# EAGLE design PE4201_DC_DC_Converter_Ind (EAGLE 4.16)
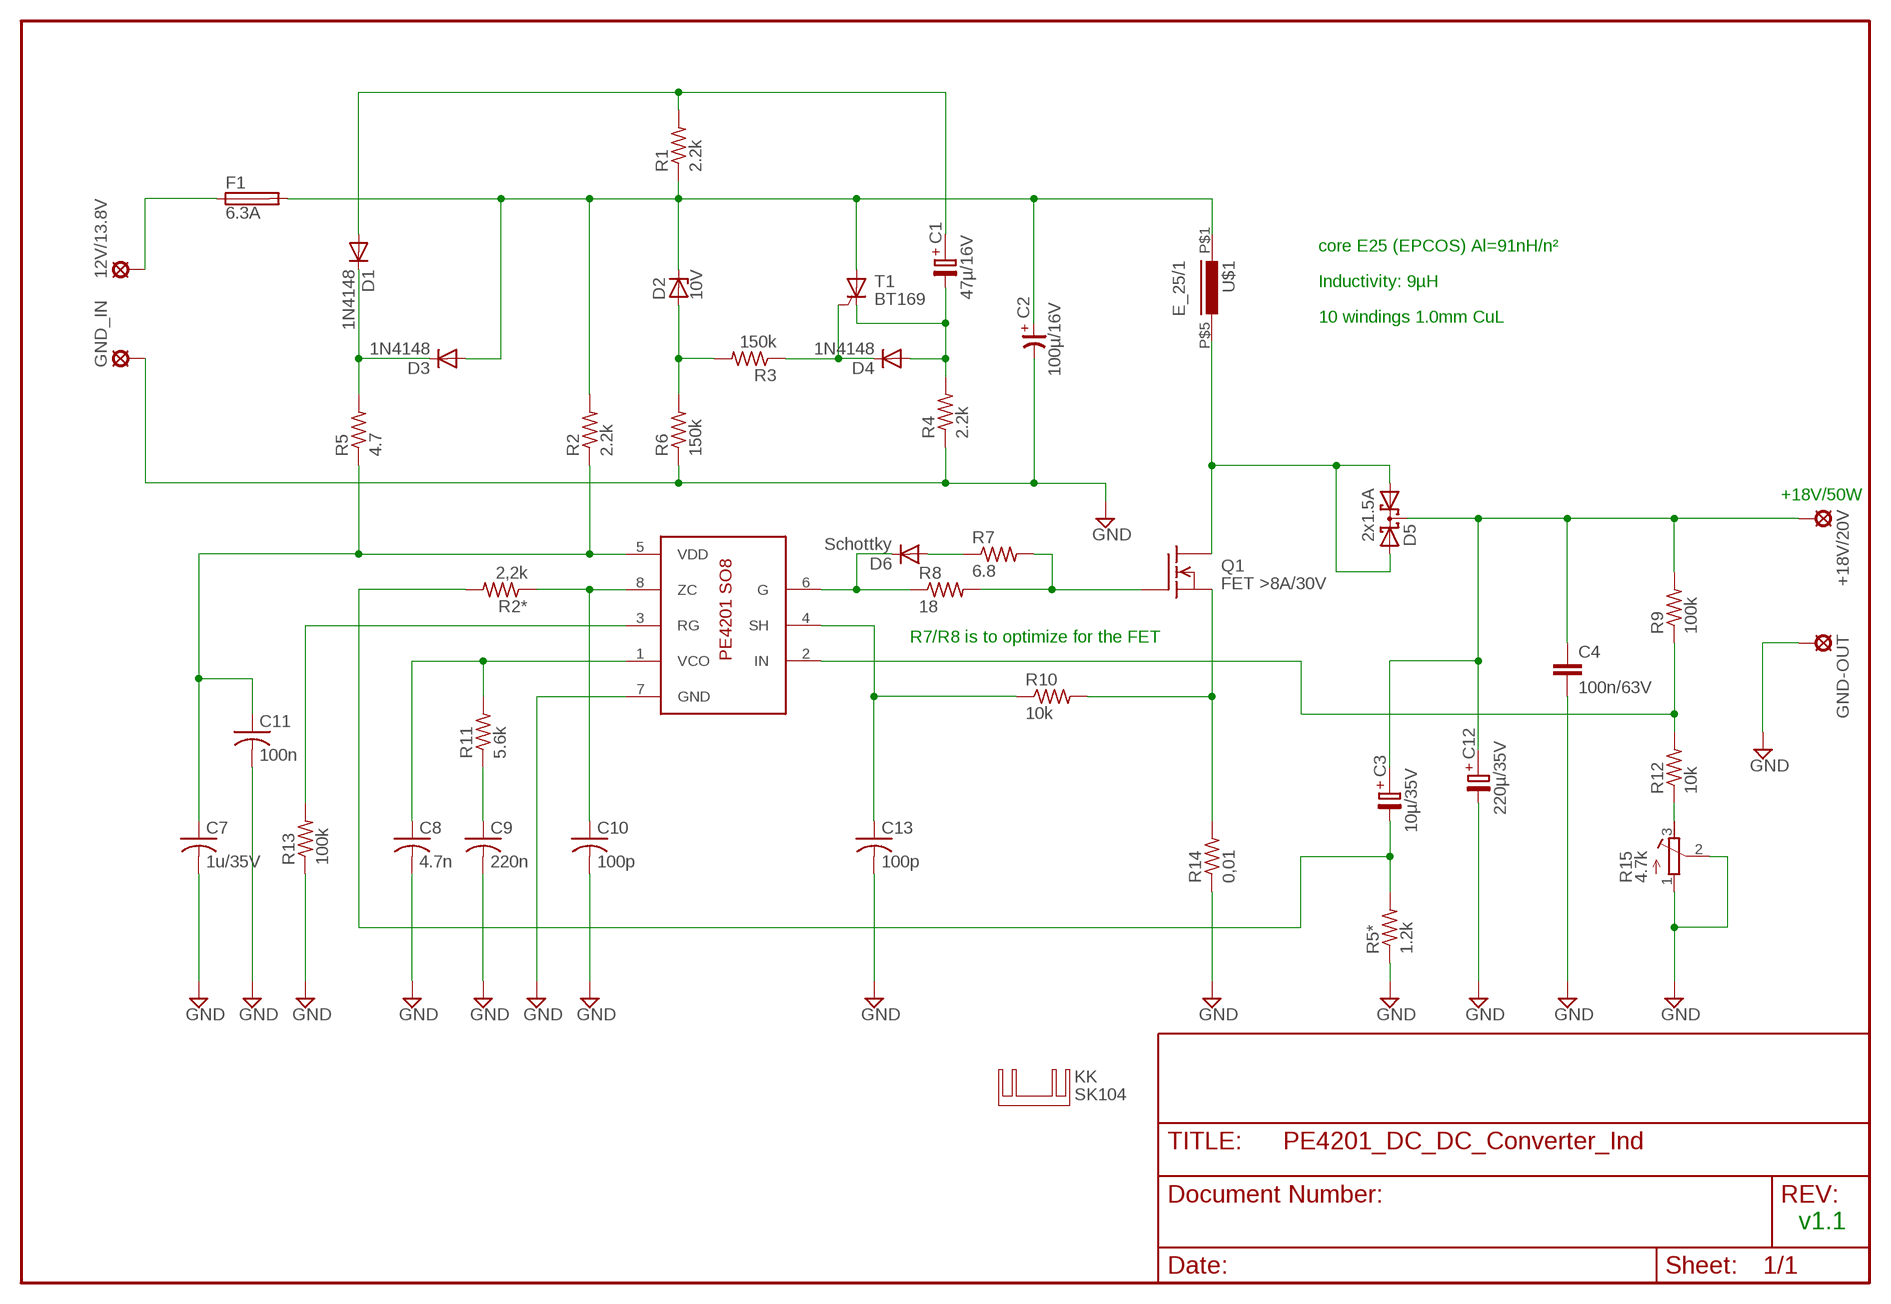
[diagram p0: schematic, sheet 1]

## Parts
12V/13.8V  SE14  [SE14]
+18V/20V  SE14  [SE14]
C1  47µ/16V  C-PR-2,5X6,5  [E2,5-6,5]
C2  100µ/16V  CP-E-035X100  [E-035X100]
C3  10µ/35V  C-PR-2,5X6  [E2,5-6]
C4  100n/63V  C7.5/4  [C7.5B4]
C7  1u/35V  C-US050-030X075  [C050-030X075]
C8  4.7n  C-US050-030X075  [C050-030X075]
C9  220n  C-US050-030X075  [C050-030X075]
C10  100p  C-US050-030X075  [C050-030X075]
C11  100n  C-US050-030X075  [C050-030X075]
C12  220µ/35V  C-PR-5,0X12  [E5,0-12]
C13  100p  C-US050-030X075  [C050-030X075]
D1  1N4148  [DO35-10]
D2  10V  ZENER-DIODEDO35Z10  [DO35Z10]
D3  1N4148  [DO35-10]
D4  1N4148  [DO35-10]
D5  2x1.5A  DIODE_2SCHOTTKY-SOT82V  [SOT82S]
D6  Schottky  1N4148  [DO35-10]
F1  6.3A  SH22,5A  [SH22,5A]
GND-OUT  SE14  [SE14]
GND_IN  GND  SE14  [SE14]
KK  SK104  [SK104]
Q1  FET >8A/30V  FQA24N50  [TOP3V]
R1  2.2k  R-US_0207/10  [0207/10]
R2  2.2k  R-US_0207/10  [0207/10]
R2*  2,2k  R-US_0207/10  [0207/10]
R3  150k  R-US_0207/10  [0207/10]
R4  2.2k  R-US_0207/10  [0207/10]
R5  4.7  R-US_0207/10  [0207/10]
R5*  1.2k  R-US_0207/10  [0207/10]
R6  150k  R-US_0207/10  [0207/10]
R7  6.8  R-US_0207/10  [0207/10]
R8  18  R-US_0207/10  [0207/10]
R9  100k  R-US_0207/10  [0207/10]
R10  10k  R-US_0207/10  [0207/10]
R11  5.6k  R-US_0207/10  [0207/10]
R12  10k  R-US_0207/10  [0207/10]
R13  100k  R-US_0207/10  [0207/10]
R14  0,01  R-US_0617/22  [0617/22]
R15  4.7k  R-TRIMM3339P  [RTRIM3339P]
T1  BT169  [TO92-2]
U$1  E_25/1  [E25L]
U$2  PE4201/4301_SO08  PE4201_SO08  [PE4201_SO08]

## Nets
++: C13.1 R10.1 U$2.4(SH)
A1: C7.1 C11.1 R2.1 R5.1 U$2.5(VDD)
A3: R13.2 U$2.3(RG)
A4: C8.1 R11.2 U$2.1(VCO)
B3: R9.1 R12.2 U$2.2(IN)
CS/ZC: C10.1 R2*.1 U$2.8(ZC)
GND: C2.- C4.2 C7.2 C8.2 C9.2 C10.2 C11.2 C12.- C13.2 GND-OUT.MP GND_IN.MP R4.1 R5*.1 R6.1 R13.1 R14.1 R15.1(E) R15.2(S) U$2.7(GND)
N$1: D4.C R3.1 T1.G
N$2: C1.- D4.A R4.2 T1.C
N$3: D2.A R3.2 R6.2
N$4: C1.+ D1.A R1.2
N$5: C2.+ D2.C D3.A F1.2 R1.1 R2.2 T1.A U$1.P$1
N$6: D6.C R8.1 U$2.6(G)
N$7: D1.C D3.C R5.2
N$8: Q1.S R10.2 R14.2
N$9: D6.A R7.1
N$10: Q1.G R7.2 R8.2
N$11: D5.A1 D5.A2 Q1.D U$1.P$5
N$12: 12V/13.8V.MP F1.1
N$19: +18V/20V.MP C3.+ C4.1 C12.+ D5.C R9.2
N$22: C9.1 R11.1
N$28: R12.1 R15.3(A)
N$29: C3.- R2*.2 R5*.2

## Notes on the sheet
- core E25 (EPCOS) Al=91nH/n²
- Inductivity: 9µH
- 10 windings 1.0mm CuL
- +18V/50W
- R7/R8 is to optimize for the FET
- v1.1

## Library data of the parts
12V/13.8V +18V/20V GND-OUT GND_IN = solpad:SE14: SOLDER PAD
C1 C3 C12 = cap-pan40:C-PR: POLARIZED ELECTROLYTIC/TANTALUM
C2 = cap-master:CP-: POLARIZED CAP
C4 = capacitor-wima:C: CAPACITOR
C7-C11 C13 = rcl:C-US: CAPACITOR, American symbol
D1 D3 D4 D6 = diode:1N4148: DIODE
D2 = diode:ZENER-DIODE: Z-Diode
D5 = diode:DIODE_2SCHOTTKY-: Dual SCHOTTKY DIODE common cathode
F1 = fuse:SH22,5A: FUSE HOLDER
KK = heatsink:SK104: HEATSINK
Q1 = PE4201:FQA24N50: N-Channel Enhancement MOSFET 400V; 12,5A; 0,4Ohm
R1 R2 R2* R3-R5 R5* R6-R14 = rcl:R-US_: RESISTOR, American symbol
R15 = rcl:R-TRIMM: Trimm resistor
T1 = triac:BT169: THYRISTOR
U$1 = EPCOS-Trafos:E_25/1
U$2 = PE4201:PE4201_SO08

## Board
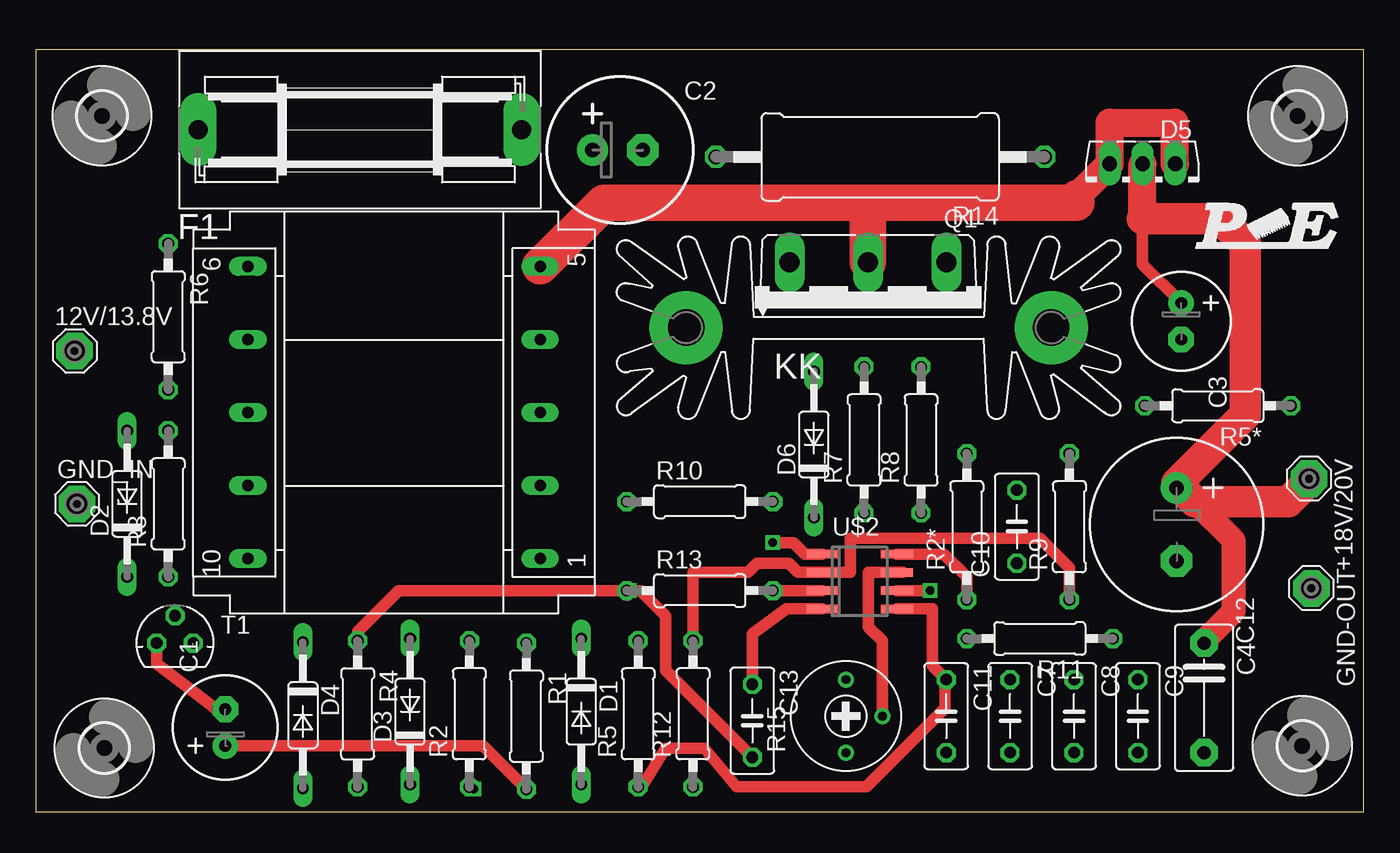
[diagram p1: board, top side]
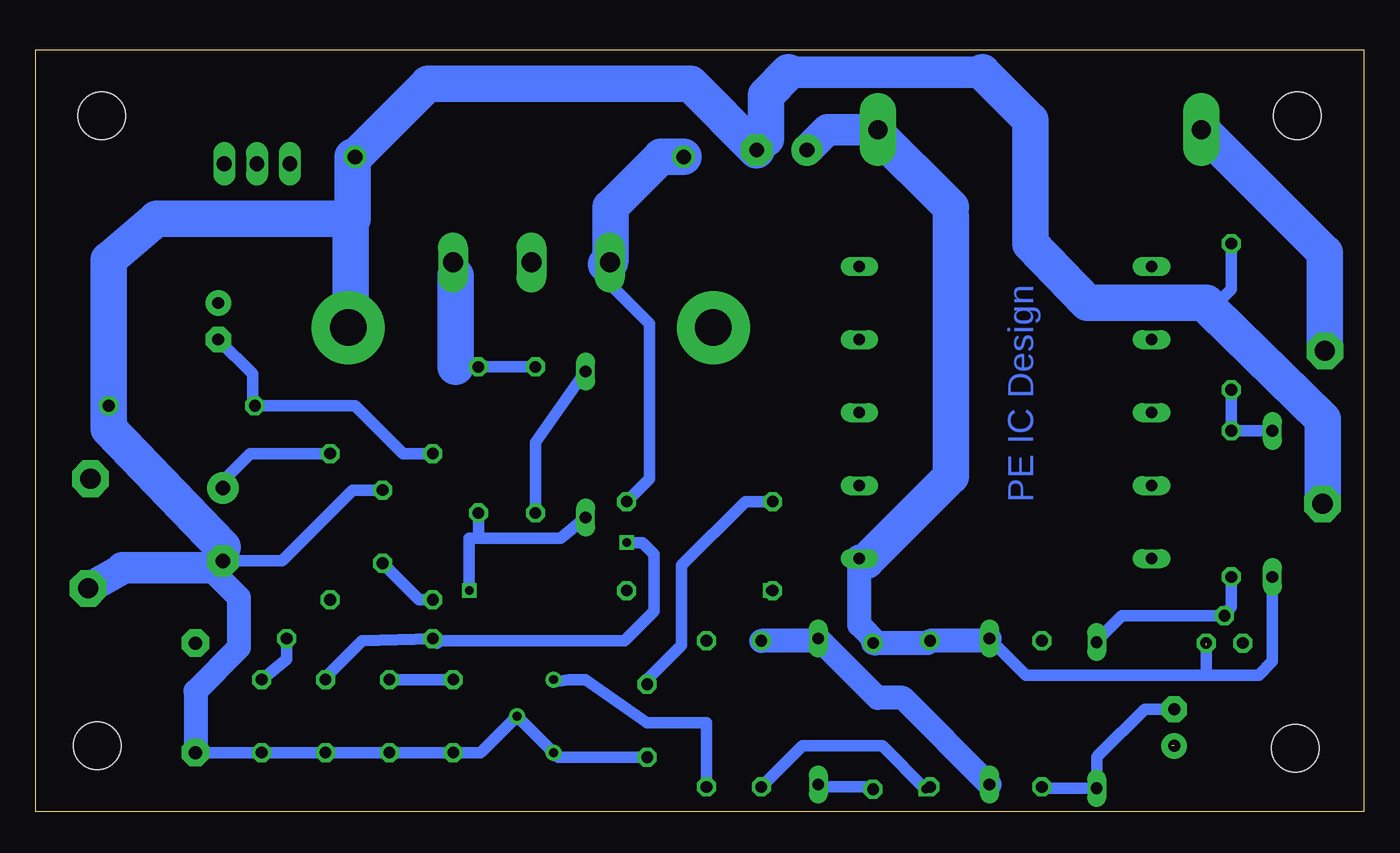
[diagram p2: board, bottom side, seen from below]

Size 92.37 x 53.01 mm. Coordinates in mm from the lower left corner, seen from the top.
Outline: 0,0 92.37,0 92.37,53.01 0,53.01 0,0
Copper layers (1*16): Top 0.035mm / dielectric 1.5mm / Bottom 0.035mm
Design rules "default": minimum track width 10mil, minimum drill 24mil, track to track 8mil, track to pad 8mil, pad to pad 8mil, via to via 8mil, smd to smd 8mil, copper to edge 40mil, drill to drill 8mil, minimum pad ring 10mil, minimum via ring 8mil, stop-mask expansion 4mil, vias tented up to drill 0mil, thermal gap 10mil

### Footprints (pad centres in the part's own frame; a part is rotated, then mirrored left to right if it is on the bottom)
SE14 = drill 1.397 pad 2.54 octagon: MP 0,0
E2,5-6,5 = drill 0.813 pad 1.778 round: + -1.27,0 | drill 0.813 pad 1.778 octagon: - 1.27,0
E-035X100 = drill 1.016 pad 2.184 round: + -1.905,0 | drill 1.016 pad 2.184 octagon: - 1.587,0
E2,5-6 = drill 0.813 pad 1.778 round: + -1.27,0 | drill 0.813 pad 1.778 octagon: - 1.27,0
C7.5B4 = drill 0.914 pad 1.905 octagon: 1 -3.81,0; 2 3.81,0
C050-030X075 = drill 0.813 octagon: 1 -2.54,0; 2 2.54,0
E5,0-12 = drill 1.016 pad 2.184 round: + -2.54,0 | drill 1.016 pad 2.184 octagon: - 2.54,0
DO35-10 = drill 0.813 long: A 5.08,0; C -5.08,0
DO35Z10 = drill 0.813 long: A 5.08,0; C -5.08,0
SOT82S = drill 1.016 long: A1 -2.286,-1.27; A2 2.286,-1.27; C 0,-1.27
SH22,5A = drill 1.321 pad 2.54 long: 1 -11.252,0; 2 11.252,0
SK104 = drill 2.54 pad 5.08 round: A2,5 -12.7,-0.762; B2,5 12.7,-0.762
TOP3V = drill 1.397 long: D 0,-3.175; G -5.461,-3.175; S 5.461,-3.175
0207/10 = drill 0.813 octagon: 1 -5.08,0; 2 5.08,0
0617/22 = drill 1.016 octagon: 1 -11.43,0; 2 11.43,0
RTRIM3339P = drill 0.61 round: 1 -2.54,0; 2 0,-2.54; 3 2.54,0
TO92-2 = drill 0.813 octagon: A 1.27,0; C -1.27,0; G 0,1.905
E25L = drill 0.8 long: P$1 -10.16,-10.16; P$2 -5.08,-10.16; P$3 0,-10.16; P$4 5.08,-10.16; P$5 10.16,-10.16; P$6 10.16,10.16; P$7 5.08,10.16; P$8 0,10.16; P$9 -5.08,10.16; P$10 -10.16,10.16
PE4201_SO08 = smd 0.6 x 2.2: 1 -1.905,-2.6; 2 -0.635,-2.6; 3 0.635,-2.6; 4 1.905,-2.6; 5 1.905,2.6; 6 0.635,2.6; 7 -0.635,2.6; 8 -1.905,2.6
3,3 = hole 3.3: 0,0

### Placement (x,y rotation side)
12V/13.8V  2.69,32.06 0 top
+18V/20V  88.58,23.17 270 top
C1  13.17,5.87 90 top
C2  40.63,46.03 0 top
C3  79.69,34.12 270 top
C4  81.28,7.93 270 top
C7  67.78,6.66 270 top
C8  72.23,6.66 270 top
C9  76.67,6.66 270 top
C10  68.26,19.84 90 top
C11  63.34,6.66 270 top
C12  79.37,20 270 top
C13  49.84,6.34 270 top
D1  37.94,6.98 270 top
D2  6.34,21.42 90 top
D3  26.03,6.98 90 top
D4  18.57,6.72 270 top
D5  76.99,43.81 180 top
D6  54.13,25.55 90 top
F1  22.54,47.46 0 top
GND-OUT  88.74,15.55 270 top
GND_IN  2.85,21.42 0 top
KK  57.94,34.44 0 top
Q1  57.89,35.05 180 top
R1  34.13,6.66 270 top
R2  30.16,6.82 90 top
R2*  64.77,19.84 90 top
R3  9.2,21.42 90 top
R4  22.38,6.82 270 top
R5  41.9,6.82 90 top
R5*  82.23,28.25 180 top
R6  9.2,34.44 270 top
R7  57.62,25.87 90 top
R8  61.59,25.87 90 top
R9  71.91,19.84 90 top
R10  46.19,21.58 0 top
R11  69.84,12.06 180 top
R12  45.71,6.82 90 top
R13  46.19,15.39 0 top
R14  58.73,45.55 180 top
R15  56.35,6.66 90 top
T1  9.68,11.74 0 top
U$1  24.92,27.77 90 top
U$2  57.3,16.03 270 top
U$3  [3,3]  4.6,48.41 0 top
U$4  [3,3]  4.76,4.44 0 top
U$5  [3,3]  88.1,4.6 0 top
U$6  [3,3]  87.78,48.41 0 top
U$7  [LOGO]  81.43,38.57 0 top

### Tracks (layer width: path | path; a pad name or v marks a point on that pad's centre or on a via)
++
  Top 0.813: U$2.4 52.22,14.12 49.84,12.38 49.84,9.2 C13.1
  Bottom 0.813: R10.1 43.02,21.58 47.46,17.14 47.46,11.58 49.84,9.2 C13.1
A1  (via drill 0.6)
  Top 0.813: U$2.5 62.38,14.12 62.38,10.15 63.24,9.3 | 63.24,9.3 C11.1 | 63.24,9.3 63.24,7.2 57.78,1.74 48.73,1.74 46.51,4.44 43.81,4.44 42.06,1.58 42.06,1.74 R5.1 | R2.1 30,1.58 v30.48,1.58
  Bottom 0.813: C7.1 67.78,9.36 67.62,9.2 C11.1 | v30.48,1.58 33.49,4.6 39.05,4.6 41.75,1.9 41.91,1.9 R5.1 | R5.1
A3
  Top 0.813: 51.11,15.55 R13.2 U$2.3
A4  (via drill 0.6)
  Top 0.813: U$2.1 53.49,17.93 52.7,18.73 v51.27,18.73
  Bottom 0.813: v51.27,18.73 50.16,18.73 49.37,17.93 49.37,13.96 51.43,11.9 64.29,11.9 64.45,11.74 R11.2 69.69,11.9 72.39,9.2 C8.1
B3
  Top 0.813: R12.2 45.72,16.66 49.53,16.66 50.16,17.3 52.38,17.3 53.02,16.66 56.51,16.66 U$2.2 56.67,16.66 56.67,19.04 62.54,19.04 65.72,19.04 69.85,19.04 71.91,16.98 R9.1 | R9.1
CS/ZC
  Top 0.813: U$2.8 63.18,17.93 64.77,16.35 R2*.1
  Bottom 0.813: R2*.1 65.72,14.76 67.94,16.98 C10.1
GND  (via drill 0.6)
  Top 0.813: 60.32,16.66 U$2.7 57.94,16.66 57.94,12.85 58.89,11.9 58.89,11.27 R15.2 | v41.27,15.39 42.06,15.39 43.81,13.65 43.81,9.84 C13.2 | C13.2 | R4.1 22.38,12.53 25.24,15.39 40.79,15.39 41.11,15.07 R13.1
  Bottom 0.813: C4.2 C9.2 C8.2 C7.2 C11.2 61.43,4.12 R15.2 R15.1 | R15.1 56.19,3.96 | 49.68,3.8 C13.2 56.03,3.8 R15.1 | v41.27,15.39 R13.1 41.11,15.23 | R6.1 9.2,36.35 10.63,34.92 | C10.2 70.32,22.38 75.24,17.46 C12.- | C12.- | C12.-
  Bottom 1.676: 80.32,16.98 78.26,14.92 78.26,11.42 81.28,8.41 C4.2
  Bottom 2.184: R14.1 70.32,45.56 | 87.31,28.41 87.47,28.41 R5*.1 | 79.37,18.41 C12.- 80.32,16.98 86.36,16.98 86.2,16.98 GND-OUT.MP | 10.63,34.92 10.95,35.39 | 26.51,51.43 40,51.43 | 42.22,46.19 | 42.22,46.19 C2.- | 41.59,46.82 42.22,46.19
  Bottom 2.54: C2.- 46.83,50.63 65.08,50.63 R14.1 | 70.32,45.56 70.32,41.27 83.97,41.27 87.31,38.41 87.31,28.41 | R5*.1 87.31,26.66 79.37,18.41 | GND_IN.MP 2.85,27.3 10.63,34.92 | 10.95,35.39 19.2,35.39 23.17,39.52 23.17,48.1 26.51,51.43 | 40,51.43 41.59,49.84 41.59,46.82
N$1  (1 unrouted)
  Bottom 0.813: R3.1 9.2,14.28 T1.G 16.82,13.65 | D4.C 18.57,11.9 16.82,13.65 | 16.82,13.65
N$2  (1 unrouted)
  Top 0.813: C1.- 12.54,7.14 11.74,7.77 8.41,10.31 T1.C
  Bottom 0.813: D4.A 18.57,1.58 | C1.- 15.24,7.14 18.41,3.96 18.57,3.8 D4.A | R4.2 22.28,1.64 D4.A
N$3  (1 unrouted)
  Bottom 0.813: R3.2 | R3.2 R6.2 | R3.2 | R3.2 D2.A 6.5,26.5
N$4  (1 unrouted)
  Top 0.813: R1.2 31.11,4.6 13.33,4.6 | C1.+ 13.33,4.76
  Bottom 0.813: D1.A 37.94,1.74 34.29,1.74 R1.2 | D1.A
N$5  (1 unrouted)
  Bottom 0.406: 6.35,14.76 | 6.35,14.76 6.35,14.92
  Bottom 0.813: 6.35,14.76 6.35,10.47 7.3,9.52 12.7,9.52 | 10.95,11.58 10.95,9.52 12.7,9.52 | 12.7,9.52 23.49,9.52 D3.A | D2.C | 6.35,14.92 D2.C | 12.7,9.52
  Bottom 1.676: 33.81,11.74 | 33.81,11.74 R1.1 30.32,11.74 R2.2 26.19,11.9 D3.A | U$1.P$1 35.08,13.01 33.81,11.74
  Bottom 1.93: U$1.P$1 35.08,17.46 34.6,17.46
  Bottom 2.184: C2.+ | C2.+ | C2.+ 37.3,47.46 F1.2 34.13,47.46 | 28.73,41.43 28.73,42.06
  Bottom 2.54: 28.73,41.43 28.73,23.33 34.6,17.46 | 28.73,42.06 34.13,47.46
N$6  (via drill 0.6)
  Top 0.813: 60.64,15.39 U$2.6 62.07,15.39 v62.23,15.39
  Bottom 0.813: D6.C 55.88,19.04 61.59,19.04 | R8.1 61.43,20.79 R8.1 61.59,19.04 | 61.59,19.04 62.23,19.04 v62.23,15.39
N$7
  Bottom 1.676: D3.C 32.06,7.93 33.81,7.93 D1.C | D1.C | D1.C 38.1,11.9 R5.2
N$8
  Bottom 0.813: R10.2 49.68,23.17 49.68,33.97 52.38,36.67 52.38,38.17 Q1.S
  Bottom 2.54: R14.2 48.89,45.55 52.38,42.06 52.38,38.41 52.57,38.22 | 52.57,38.22 52.7,38.09 | Q1.S 52.57,38.22
N$9
  Bottom 0.813: R7.1 | D6.A 57.62,25.71 R7.1
N$10
  Bottom 0.813: R7.2 63.02,30.95 R8.2 63.18,30.95 | Q1.G 63.35,38.11 62.86,37.62 63.18,37.3
  Bottom 2.54: 63.18,30.95 63.18,37.3
N$11
  Top 1.93: 72.39,42.86 | 72.39,42.86 72.48,42.86 D5.A2 74.7,47.94 79.21,47.94 79.21,45.08 D5.A1
  Top 2.184: 72.39,42.38 72.39,42.86 | U$1.P$5
  Top 2.54: 57.89,42.38 72.39,42.38 | 57.89,42.38 Q1.D | 57.89,42.38 39.52,42.38 U$1.P$5
N$12
  Bottom 2.184: 11.43,47.62 11.29,47.48 F1.1
  Bottom 2.54: 12V/13.8V.MP 2.69,38.89 11.29,47.48
N$13
  Bottom 1.676: 70.48,33.65 70.64,33.65
  Bottom 2.54: 70.48,33.65 70.48,41.59
N$19
  Top 0.813: 82.39,41.27 81.59,41.27 | D5.C 76.99,38.09 C3.+
  Top 1.676: 80.64,21.58 83.34,18.88 83.34,13.96 81.43,12.06 81.43,11.74 C4.1
  Top 1.93: 76.99,41.27 D5.C
  Top 2.184: 79.37,22.85 | 79.37,22.85 C12.+ | 79.37,22.85 84.13,27.62 84.13,39.52 82.39,41.27 | 79.37,22.85 80.64,21.58 84.93,21.58 87.15,21.58 88.74,23.17 +18V/20V.MP | 81.59,41.27 76.99,41.27
  Bottom 0.813: 79.37,23.01 79.53,22.85 | C12.+ 79.37,23.01 | R9.2 77.47,24.92 79.37,23.01
N$22
  Bottom 0.813: R11.1 74.93,10.63 C9.1
N$28
  Bottom 0.813: R15.3 56.35,9.04 55.24,9.2 54.13,9.2 49.84,6.19 45.72,6.19 45.72,4.76 R12.1
N$29
  Bottom 0.813: R2*.2 66.83,24.92 70.16,28.25 R5*.2 77.31,28.25 77.31,29.2 | 77.31,29.2 77.31,29.36 | C3.- 77.31,30.47 77.31,29.2

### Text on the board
Bottom: PE IC Design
